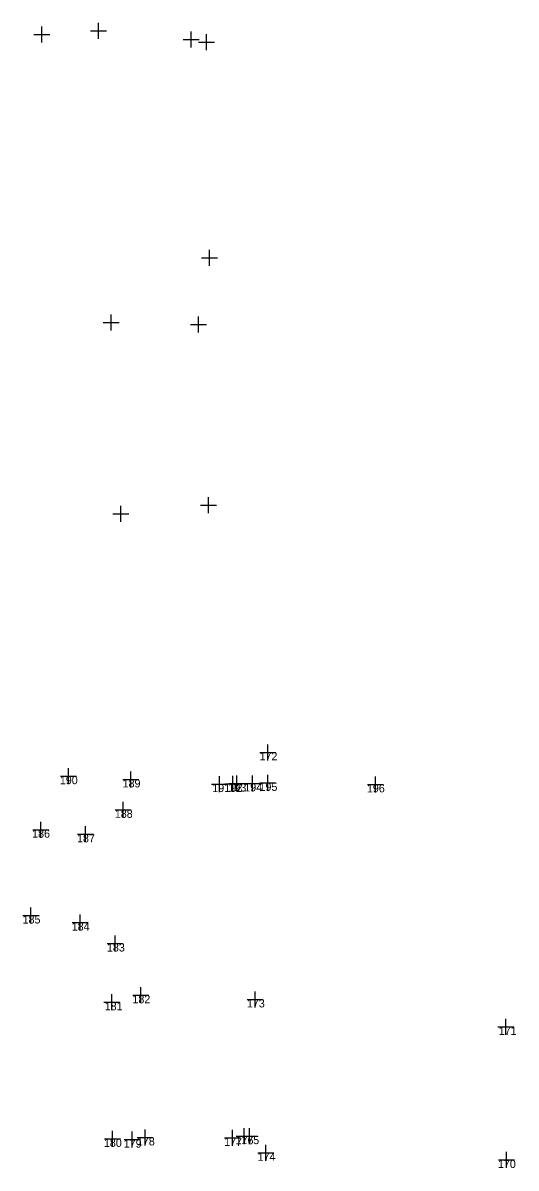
# Model space of a CAD drawing. Extents: x -706655 to -706193, y -1036183 to -1035040.
# Drawn here: x -706410.4 to -706379.6, y -1035901.5 to -1035830 of the extents above; entities that cross this region are included whole.
import ezdxf

# ---------------------------------------------------------------- set-up
doc = ezdxf.new("R2010")
doc.units = 0
doc.layers.add('čísla bodu', color=7, linetype='Continuous')

msp = doc.modelspace()

# ---------------------------------------------------------------- linework, layer by layer
at = {"layer": 'čísla bodu'}
for p, q in [((-706409.25, -1035831.24), (-706409.25, -1035830.24)), ((-706409.25, -1035831.24), (-706409.25, -1035830.24)), ((-706405.71, -1035831.01), (-706405.71, -1035830.01)), ((-706405.71, -1035831.01), (-706405.71, -1035830.01)), ((-706409.75, -1035830.74), (-706408.75, -1035830.74)), ((-706409.75, -1035830.74), (-706408.75, -1035830.74)), ((-706409.25, -1035830.74), (-706409.25, -1035830.74)), ((-706409.25, -1035830.74), (-706409.25, -1035830.74)), ((-706406.21, -1035830.51), (-706405.21, -1035830.51)), ((-706406.21, -1035830.51), (-706405.21, -1035830.51)), ((-706405.71, -1035830.51), (-706405.71, -1035830.51)), ((-706405.71, -1035830.51), (-706405.71, -1035830.51)), ((-706400.43, -1035831.04), (-706399.43, -1035831.04)), ((-706400.43, -1035831.04), (-706399.43, -1035831.04)), ((-706399.93, -1035831.54), (-706399.93, -1035830.54)), ((-706399.93, -1035831.54), (-706399.93, -1035830.54)), ((-706399.93, -1035831.04), (-706399.93, -1035831.04)), ((-706399.93, -1035831.04), (-706399.93, -1035831.04)), ((-706398.96, -1035831.71), (-706398.96, -1035830.71)), ((-706398.96, -1035831.71), (-706398.96, -1035830.71)), ((-706399.46, -1035831.21), (-706398.46, -1035831.21)), ((-706399.46, -1035831.21), (-706398.46, -1035831.21)), ((-706398.96, -1035831.21), (-706398.96, -1035831.21)), ((-706398.96, -1035831.21), (-706398.96, -1035831.21)), ((-706399.28, -1035844.68), (-706398.28, -1035844.68)), ((-706399.28, -1035844.68), (-706398.28, -1035844.68)), ((-706398.78, -1035845.18), (-706398.78, -1035844.18)), ((-706398.78, -1035845.18), (-706398.78, -1035844.18)), ((-706398.78, -1035844.68), (-706398.78, -1035844.68)), ((-706398.78, -1035844.68), (-706398.78, -1035844.68)), ((-706404.91, -1035849.23), (-706404.91, -1035848.23)), ((-706404.91, -1035849.23), (-706404.91, -1035848.23)), ((-706405.41, -1035848.73), (-706404.41, -1035848.73)), ((-706405.41, -1035848.73), (-706404.41, -1035848.73)), ((-706404.91, -1035848.73), (-706404.91, -1035848.73)), ((-706404.91, -1035848.73), (-706404.91, -1035848.73)), ((-706399.97, -1035848.85), (-706398.97, -1035848.85)), ((-706399.97, -1035848.85), (-706398.97, -1035848.85)), ((-706399.47, -1035849.35), (-706399.47, -1035848.35)), ((-706399.47, -1035849.35), (-706399.47, -1035848.35)), ((-706399.47, -1035848.85), (-706399.47, -1035848.85)), ((-706399.47, -1035848.85), (-706399.47, -1035848.85)), ((-706398.83, -1035860.63), (-706398.83, -1035859.63)), ((-706398.83, -1035860.63), (-706398.83, -1035859.63)), ((-706404.32, -1035861.17), (-706404.32, -1035860.17)), ((-706404.32, -1035861.17), (-706404.32, -1035860.17)), ((-706399.33, -1035860.13), (-706398.33, -1035860.13)), ((-706399.33, -1035860.13), (-706398.33, -1035860.13)), ((-706398.83, -1035860.13), (-706398.83, -1035860.13)), ((-706398.83, -1035860.13), (-706398.83, -1035860.13)), ((-706404.82, -1035860.67), (-706403.82, -1035860.67)), ((-706404.82, -1035860.67), (-706403.82, -1035860.67)), ((-706404.32, -1035860.67), (-706404.32, -1035860.67)), ((-706404.32, -1035860.67), (-706404.32, -1035860.67)), ((-706395.13, -1035876.07), (-706395.13, -1035875.07)), ((-706395.63, -1035875.57), (-706394.63, -1035875.57)), ((-706395.13, -1035875.57), (-706395.13, -1035875.57)), ((-706407.58, -1035877.56), (-706407.58, -1035876.56)), ((-706403.68, -1035877.76), (-706403.68, -1035876.76)), ((-706408.08, -1035877.06), (-706407.08, -1035877.06)), ((-706407.58, -1035877.06), (-706407.58, -1035877.06)), ((-706404.18, -1035877.26), (-706403.18, -1035877.26)), ((-706403.68, -1035877.26), (-706403.68, -1035877.26)), ((-706398.65, -1035877.55), (-706397.65, -1035877.55)), ((-706398.15, -1035878.05), (-706398.15, -1035877.05)), ((-706398.15, -1035877.55), (-706398.15, -1035877.55)), ((-706397.82, -1035877.54), (-706396.82, -1035877.54)), ((-706397.57, -1035877.52), (-706396.57, -1035877.52)), ((-706397.32, -1035878.04), (-706397.32, -1035877.04)), ((-706397.32, -1035877.54), (-706397.32, -1035877.54)), ((-706397.07, -1035878.02), (-706397.07, -1035877.02)), ((-706397.07, -1035877.52), (-706397.07, -1035877.52)), ((-706396.58, -1035877.51), (-706395.58, -1035877.51)), ((-706396.08, -1035878.01), (-706396.08, -1035877.01)), ((-706396.08, -1035877.51), (-706396.08, -1035877.51)), ((-706395.63, -1035877.48), (-706394.63, -1035877.48)), ((-706395.13, -1035877.98), (-706395.13, -1035876.98)), ((-706395.13, -1035877.48), (-706395.13, -1035877.48)), ((-706388.91, -1035877.57), (-706387.91, -1035877.57)), ((-706388.41, -1035878.07), (-706388.41, -1035877.07)), ((-706388.41, -1035877.57), (-706388.41, -1035877.57)), ((-706404.17, -1035879.66), (-706404.17, -1035878.66)), ((-706404.67, -1035879.16), (-706403.67, -1035879.16)), ((-706404.17, -1035879.16), (-706404.17, -1035879.16)), ((-706409.82, -1035880.4), (-706408.82, -1035880.4)), ((-706409.32, -1035880.9), (-706409.32, -1035879.9)), ((-706409.32, -1035880.4), (-706409.32, -1035880.4)), ((-706406.53, -1035881.19), (-706406.53, -1035880.19)), ((-706407.03, -1035880.69), (-706406.03, -1035880.69)), ((-706406.53, -1035880.69), (-706406.53, -1035880.69)), ((-706409.93, -1035886.26), (-706409.93, -1035885.26)), ((-706410.43, -1035885.76), (-706409.43, -1035885.76)), ((-706409.93, -1035885.76), (-706409.93, -1035885.76)), ((-706406.86, -1035886.7), (-706406.86, -1035885.7)), ((-706407.36, -1035886.2), (-706406.36, -1035886.2)), ((-706406.86, -1035886.2), (-706406.86, -1035886.2)), ((-706405.16, -1035887.51), (-706404.16, -1035887.51)), ((-706404.66, -1035888.01), (-706404.66, -1035887.01)), ((-706404.66, -1035887.51), (-706404.66, -1035887.51)), ((-706403.07, -1035891.24), (-706403.07, -1035890.24)), ((-706405.37, -1035891.18), (-706404.37, -1035891.18)), ((-706404.87, -1035891.68), (-706404.87, -1035890.68)), ((-706404.87, -1035891.18), (-706404.87, -1035891.18)), ((-706403.57, -1035890.74), (-706402.57, -1035890.74)), ((-706403.07, -1035890.74), (-706403.07, -1035890.74)), ((-706396.42, -1035891), (-706395.42, -1035891)), ((-706395.92, -1035891.5), (-706395.92, -1035890.5)), ((-706395.92, -1035891), (-706395.92, -1035891)), ((-706380.26, -1035893.22), (-706380.26, -1035892.22)), ((-706380.76, -1035892.72), (-706379.76, -1035892.72)), ((-706380.26, -1035892.72), (-706380.26, -1035892.72)), ((-706396.61, -1035900.05), (-706396.61, -1035899.05)), ((-706396.27, -1035900.04), (-706396.27, -1035899.04)), ((-706405.33, -1035899.71), (-706404.33, -1035899.71)), ((-706404.83, -1035900.21), (-706404.83, -1035899.21)), ((-706404.83, -1035899.71), (-706404.83, -1035899.71)), ((-706404.11, -1035899.76), (-706403.11, -1035899.76)), ((-706403.61, -1035900.26), (-706403.61, -1035899.26)), ((-706403.61, -1035899.76), (-706403.61, -1035899.76)), ((-706403.29, -1035899.62), (-706402.29, -1035899.62)), ((-706402.79, -1035900.12), (-706402.79, -1035899.12)), ((-706402.79, -1035899.62), (-706402.79, -1035899.62)), ((-706397.84, -1035899.65), (-706396.84, -1035899.65)), ((-706397.34, -1035900.15), (-706397.34, -1035899.15)), ((-706397.34, -1035899.65), (-706397.34, -1035899.65)), ((-706397.11, -1035899.55), (-706396.11, -1035899.55)), ((-706396.77, -1035899.54), (-706395.77, -1035899.54)), ((-706396.61, -1035899.55), (-706396.61, -1035899.55)), ((-706396.27, -1035899.54), (-706396.27, -1035899.54)), ((-706395.25, -1035901.08), (-706395.25, -1035900.08)), ((-706395.75, -1035900.58), (-706394.75, -1035900.58)), ((-706395.25, -1035900.58), (-706395.25, -1035900.58)), ((-706380.72, -1035901.03), (-706379.72, -1035901.03)), ((-706380.22, -1035901.53), (-706380.22, -1035900.53)), ((-706380.22, -1035901.03), (-706380.22, -1035901.03))]:
    msp.add_line(p, q, dxfattribs=at)

# ---------------------------------------------------------------- texts
for s, p in [('172', (-706395.65, -1035876.07)), ('190', (-706408.123, -1035877.56)), ('189', (-706404.202, -1035877.76)), ('191', (-706398.602, -1035878.05)), ('192', (-706397.842, -1035878.04)), ('193', (-706397.592, -1035878.02)), ('194', (-706396.602, -1035878.01)), ('195', (-706395.652, -1035877.98)), ('196', (-706388.945, -1035878.07)), ('188', (-706404.69, -1035879.66)), ('186', (-706409.854, -1035880.9)), ('187', (-706407.05, -1035881.19)), ('185', (-706410.45, -1035886.26)), ('184', (-706407.38, -1035886.7)), ('183', (-706405.18, -1035888.01)), ('181', (-706405.32, -1035891.68)), ('182', (-706403.59, -1035891.24)), ('173', (-706396.44, -1035891.5)), ('171', (-706380.71, -1035893.22)), ('180', (-706405.371, -1035900.21)), ('179', (-706404.132, -1035900.26)), ('178', (-706403.31, -1035900.12)), ('177', (-706397.86, -1035900.15)), ('176', (-706397.144, -1035900.05)), ('175', (-706396.79, -1035900.04)), ('174', (-706395.77, -1035901.08)), ('170', (-706380.761, -1035901.53))]:
    msp.add_text(s, height=0.5, dxfattribs=at).set_placement(p)

doc.saveas('drawing.dxf')
